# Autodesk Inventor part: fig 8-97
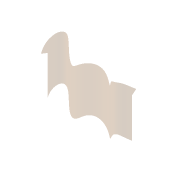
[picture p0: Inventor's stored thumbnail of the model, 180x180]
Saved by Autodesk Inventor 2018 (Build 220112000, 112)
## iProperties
Shininess: 64.0
Length Units: 11269
Angle Units: 11279
Time Units: 11290
Mass Units: 11283
Length Display Precision: 3
Angle Display Precision: 2
Compacted: True
Part Number: fig 8-97
Document SubType Name: Modeling
Created: 2003-08
Designer: Owner
Manufacturer: Standard
Standards Organization: Custom
Density: 1 g/cm^3
Material: Generic
Appearance: Default
Density: 0.0
Volumn: 0.0
Area: 0.0
PropertySet Name: Model Information
Control State: 0
Master: False
Checked Out: False
Author: Owner
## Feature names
1. Split6
## Parameters: d3 = 0, d5 = 0, d6 = 0, d8 = 0
